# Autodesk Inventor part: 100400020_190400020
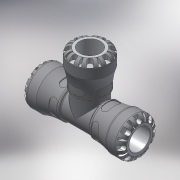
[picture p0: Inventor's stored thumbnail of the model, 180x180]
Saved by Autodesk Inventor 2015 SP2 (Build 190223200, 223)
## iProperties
Created: 2016-12
Part Number: 100400020_190400020
Material: Generic
Description: PLASSON TEE 20X20X20 SERIES 1
Document SubType Name: Modeling
Designer: KIM
Mass: 664.223 g
Surface Area: 733.008 cm^2
Volume: 474.445 cm^3
Density: 1 g/cm^3
Appearance: Default
Author: KIM
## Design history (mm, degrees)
derived "1004.ipt"
feature "Solid1::1004.ipt"
tag "TaggingFeature1"
body "Solid1"
other parameters: "d1" = 18.9, "d3" = 25, "d4" = 41, "d8" = 34.85, "d13" = 6.4, "d14" = 6.4, "d15" = 0, "d17" = 360 deg, "d19" = 8 deg, "d20" = 0.4, "d21" = 0.4, "d22" = 8 deg, "d24" = 0, "d26" = 360 deg, "d33" = 4.1, "d43" = 31.98, "d51" = 0.41, "d54" = 7, "d55" = 4.4, "d57" = 12.544, "d58" = 0, "d74" = 0, "d77" = 1.66667, "d78" = 45, "d79" = 31.98, "d80" = 123, "d82" = 0.4, "d115" = 360 deg, "d139" = 6.4, "d140" = 0, "d142" = 360 deg, "d207" = 90 deg, "d209" = 18.9, "d211" = 25, "d212" = 41, "d213" = 34.85, "d215" = 31.98, "d216" = 1.66667, "d217" = 45, "d225" = 71, "d226" = 45, "d228" = 5.95, "d229" = 6.4, "d233" = 6.4, "d234" = 0, "d236" = 360 deg, "d238" = 8 deg, "d239" = 8 deg, "d240" = 0.4, "d241" = 0.4, "d243" = 0, "d245" = 360 deg, "d247" = 0.82, "d248" = 2.7, "d249" = 2.7, "d250" = 5.95, "d252" = 7, "d253" = 4.6, "d254" = 12.544, "d255" = 0, "d257" = 360 deg, "d259" = 0.4, "d261" = 0, "d262" = 0.82, "d264" = 0, "d266" = 0, "d267" = 0.41, "E_" = 41, "l_" = 45, "A_" = 71, "H_" = 123, "d9" = 8, "d11" = 41, "d12" = 25, "d230" = 41, "d231" = 25, "d232" = 8
